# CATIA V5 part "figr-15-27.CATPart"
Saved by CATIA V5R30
Part number: Part1
Bounding box of the stored display mesh (mm): x -61.282 to 61.282, y -26.72 to 26.72, z 0 to 0.75
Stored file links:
  D:\PROJECTS\CATIA V56R 2020\Resources\Parts File\c15_catia_v5_6r2020_prt\figr-15-27.CATPart
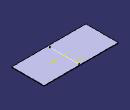
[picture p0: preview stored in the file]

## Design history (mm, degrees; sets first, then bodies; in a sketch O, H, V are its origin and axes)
SheetMetalParameters1: Thickness 0.75, BendRadius 1, KFactor 0.356492 {= log(min(100,max(20*SheetMetalParameters1.BendRadius,SheetMetalParameters1.Thickness)/SheetMetalParameters1.Thickness))/log(100)/2}, ReliefRadialLength 1, ReliefAxialLength 2, MinimumBendRadius 0
Body1 (main body)
  Sketch1 on xy-plane, origin (0, 0, 0), H (1, 0, 0), V (0, 1, 0)
    line L1 (61.282, 26.7197) -> (61.282, -26.7197)
    line L2 (61.282, -26.7197) -> (-61.282, -26.7197)
    line L3 (-61.282, -26.7197) -> (-61.282, 26.7197)
    line L4 (-61.282, 26.7197) -> (61.282, 26.7197)
    vertical: L1 V, L3 V
    horizontal: L2 H, L4 H
    equidistance: L1 L3 O, L2 L4 O
  Wall1: Thickness 0.75, Profile Sketch1
  Sketch2 on face of Wall1, origin (0, 0, 0.75), H (1, 0, 0), V (0, 1, 0)
    line L1 (1.9015, 25.4615) -> (1.9015, -22.9675)
    vertical: L1 V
